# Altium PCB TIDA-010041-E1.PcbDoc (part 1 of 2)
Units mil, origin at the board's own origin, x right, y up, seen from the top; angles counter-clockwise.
Board outline 3937.01 x 2165.35 mil, 2 copper layers (Top Layer, Bottom Layer), stack 62 mil thick; 146 components, 79 nets, 325 pads, 93 vias.
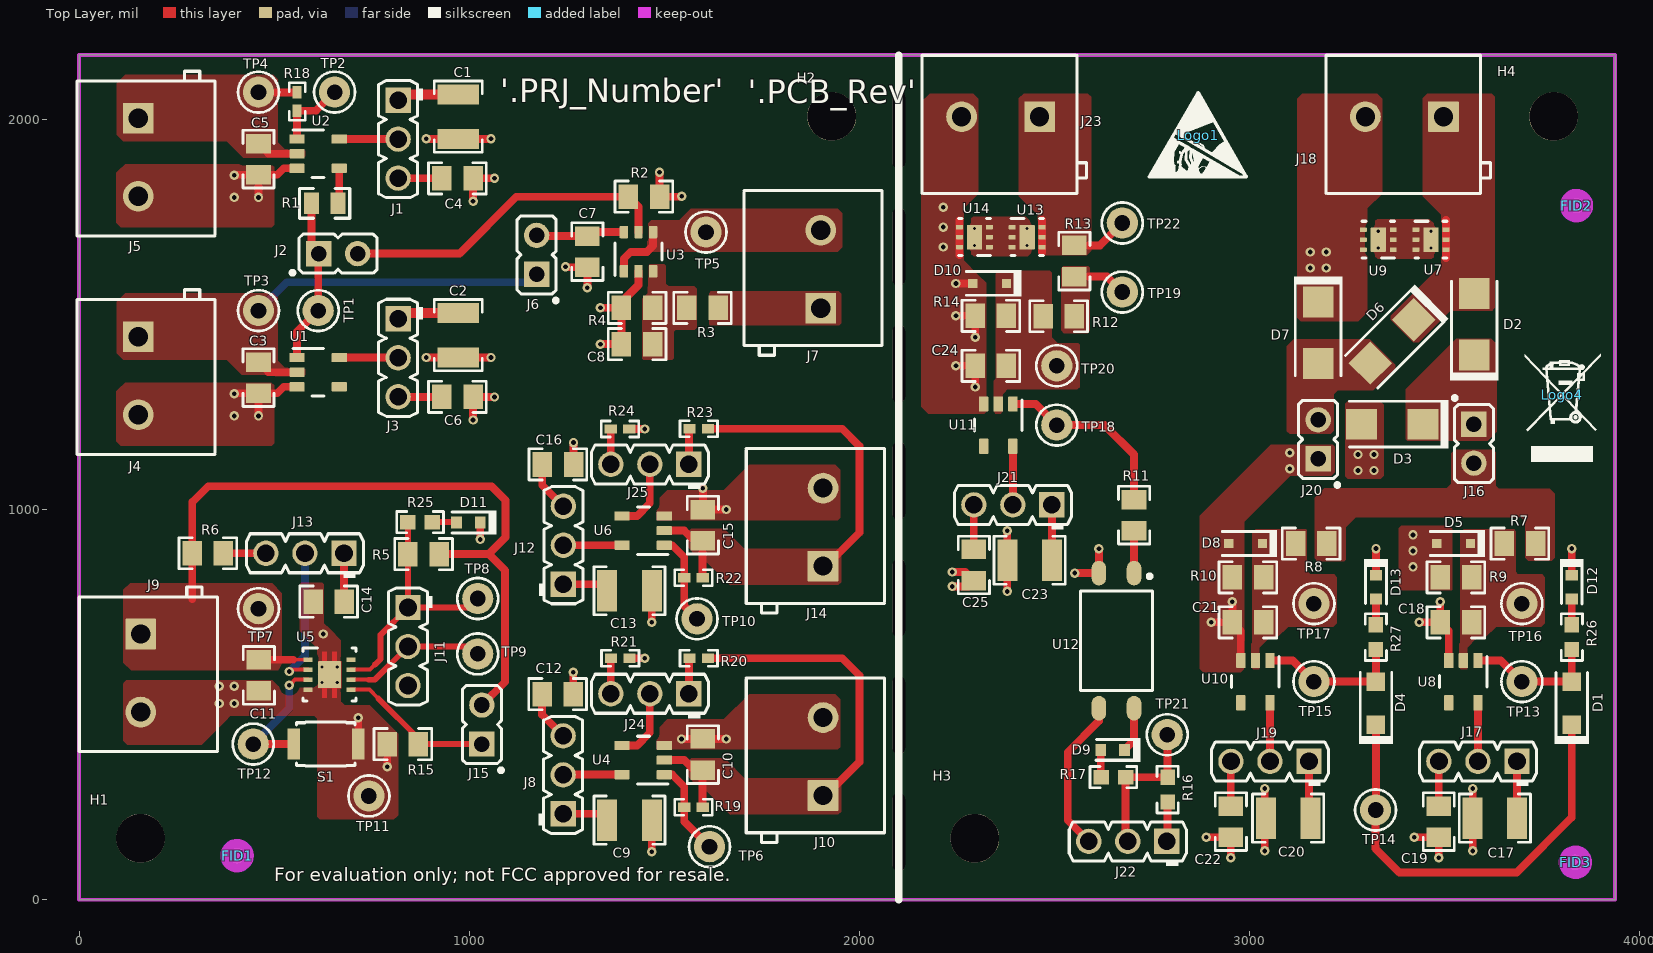
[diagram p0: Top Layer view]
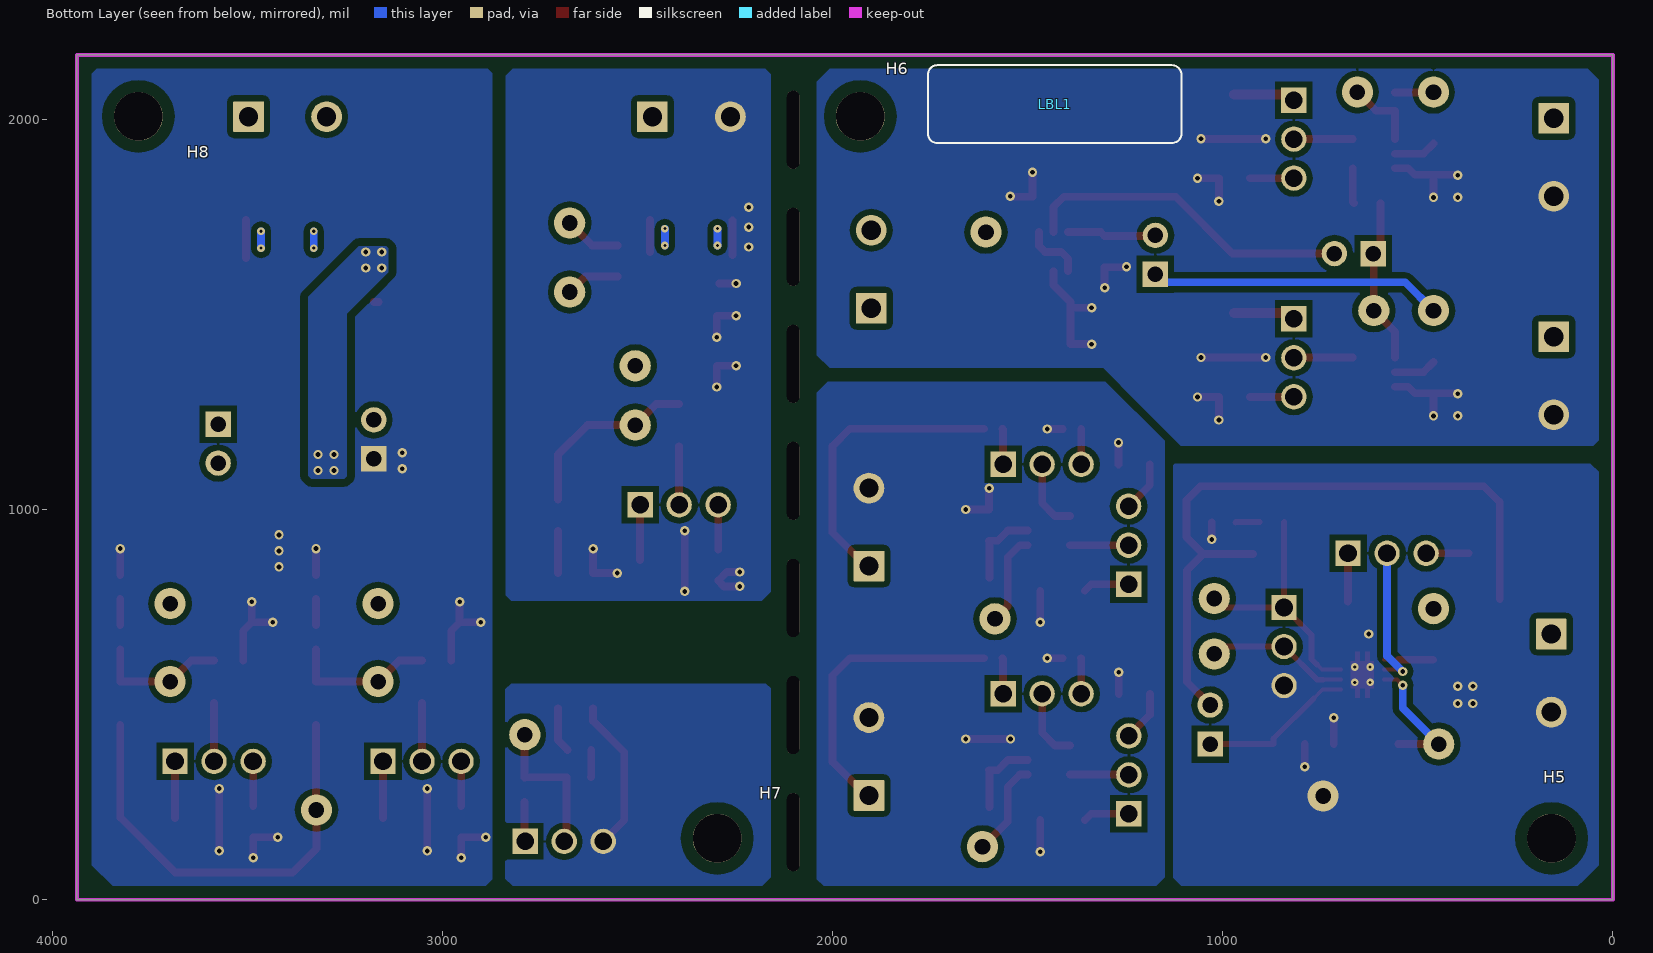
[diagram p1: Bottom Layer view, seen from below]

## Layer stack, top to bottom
Top Solder: solder mask 0.4, Solder Resist, Dk 3.5
Top Layer: signal copper 1.4
Dielectric1: core 59.2, FR-4 High Tg, Dk 4.8
Bottom Layer: signal copper 1.4
Bottom Solder: solder mask 0.4, Solder Resist, Dk 3.5

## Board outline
0,0 3937.01,0 3937.01,2165.35 0,2165.35

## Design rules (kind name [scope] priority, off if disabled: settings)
AcuteAngle [All] p1: minimum=4.50000000000000E+0001 checktracksonly=FALSE
AssemblyTestPointUsage [All] p1: valid=2
BoardOutlineClearance BoardOutlineClearance_MountingHoles [OnCopper and InComponentClass('Mounting Holes')] p1: gap=30 ignorepadtopadclearanceinfootprint=FALSE
BoardOutlineClearance BoardOutlineClearance_Poly [OnCopper and InPoly] p2: gap=25 ignorepadtopadclearanceinfootprint=FALSE
BoardOutlineClearance [OnCopper and Not InComponentClass('Logo') and not InComponentClass('FiducialMark') and not InRegion(1000,500,4000,800)] p3: gap=15 ignorepadtopadclearanceinfootprint=FALSE
Clearance Clearance_MH [InPadClass('MH') vs InPoly] p1: gap=30 ignorepadtopadclearanceinfootprint=FALSE except(0: Arc-Hole Track-Hole SMDPad-Hole THPad-Hole Via-Hole Fill-Hole Poly-Hole Region-Hole Text-Hole)
Clearance Clearance_Poly_poly [InPoly vs InPoly] p2: gap=20 ignorepadtopadclearanceinfootprint=FALSE except(0: Arc-Hole Track-Hole SMDPad-Hole THPad-Hole Via-Hole Fill-Hole Poly-Hole Region-Hole Text-Hole)
Clearance Clearance_Keepouts [IsKeepOut vs InPoly] p3: gap=30 ignorepadtopadclearanceinfootprint=FALSE except(0: Arc-Hole Track-Hole SMDPad-Hole THPad-Hole Via-Hole Fill-Hole Poly-Hole Region-Hole Text-Hole)
Clearance Clearance_Poly [InPolygon] p4: gap=15 ignorepadtopadclearanceinfootprint=FALSE except(0: Arc-Hole Track-Hole SMDPad-Hole THPad-Hole Via-Hole Fill-Hole Poly-Hole Region-Hole Text-Hole)
Clearance [All] p5: gap=7.87 ignorepadtopadclearanceinfootprint=FALSE except(0: Arc-Arc Arc-SMDPad Arc-Hole Track-Hole SMDPad-Hole THPad-Hole Via-Hole Fill-Hole Poly-Hole Region-Hole Text-Hole)
ComponentClearance ComponentClearance_MountingHoles_FiducialMarks [InComponentClass('Mounting Holes') vs InComponentClass('FiducialMark')] p1: gap=10 collisioncheckmode=3 verticalgap=10 showdistances=FALSE
ComponentClearance ComponentClearance_Shunt [InComponentClass('Header') vs InComponentClass('Shunt')] p2: gap=0 collisioncheckmode=3 verticalgap=0 showdistances=FALSE
ComponentClearance ComponentClearance_Logo [InComponentClass('Logo')] p3: gap=5 collisioncheckmode=3 verticalgap=5 showdistances=FALSE
ComponentClearance ComponentClearance_ScrewToNut [(HasFootprint('NY PMS 440 0025 PH')) vs (HasFootprint('Keystone_1902C'))] p4: gap=5 collisioncheckmode=3 verticalgap=10 showdistances=FALSE
ComponentClearance ComponentClearance_MountingHoles [InComponentClass('Mounting Holes')] p5: gap=250 collisioncheckmode=3 verticalgap=100000 showdistances=FALSE
ComponentClearance ComponentClearance_SmallPassives [HasFootprint('0201*') or HasFootprint('0402*') or HasFootprint('0508') or HasFootprint('0603*') or HasFootprint('0612') or HasFootprint('0805*') or HasFootprint('0815*') or HasFootprint('0830*') or HasFootprint('1206*') or HasFootprint('1210*') or HasFootprint('1808*') or HasFootprint('1812*') or HasFootprint('1825*') or HasFootprint('2010*') or HasFootprint('2220*') or HasFootprint('2225*') or HasFootprint('2512*') or HasFootprint('2728*') or HasFootprint('3518*') vs HasFootprint('0201*') or HasFootprint('0402*') or HasFootprint('0508') or HasFootprint('0603*') or HasFootprint('0612') or HasFootprint('0805*') or HasFootprint('0815*') or HasFootprint('0830*') or HasFootprint('1206*') or HasFootprint('1210*') or HasFootprint('1808*') or HasFootprint('1812*') or HasFootprint('1825*') or HasFootprint('2010*') or HasFootprint('2220*') or HasFootprint('2225*') or HasFootprint('2512*') or HasFootprint('2728*') or HasFootprint('3518*')] p6: gap=5 collisioncheckmode=3 verticalgap=5 showdistances=FALSE
ComponentClearance ComponentClearance_THtoSMT [IsThruComponent vs IsSMTComponent] p7: gap=5 collisioncheckmode=3 verticalgap=5 showdistances=FALSE
ComponentClearance ComponentClearance_THtoTH [IsThruComponent vs IsThruComponent] p8: gap=0 collisioncheckmode=3 verticalgap=10 showdistances=FALSE
ComponentClearance [All] p9: gap=10 collisioncheckmode=3 verticalgap=10 showdistances=FALSE
DiffPairsRouting [All] p1: maxlimit=100 minlimit=10 mostfreqgap=10 toplayer_minwidth=15 toplayer_maxwidth=15 toplayer_prefwidth=15 bottomlayer_minwidth=15 bottomlayer_maxwidth=15 bottomlayer_prefwidth=15 maxuncoupledlength=1000
FabricationTestPointUsage TestPointUsage [All] p1: valid=2 allowmultiple=FALSE
FabricationTestpoint Testpoint [All] p1: side=3 testpointundercomponent=TRUE minsize=40 maxsize=100 preferedsize=60 minholesize=0 maxholesize=40 preferedholesize=32 testpointgrid=1 allowsidetop=TRUE allowsidebottom=TRUE usegrid=TRUE gridtolerance=0.01
FanoutControl Fanout_LCC [IsLCC] p1: bgadir=Out bgaviamode=Centered fanoutstyle=Auto fanoutdirection=Alternating viagrid=1 // Fanout_LCC (Default Rule)
FanoutControl Fanout_BGA [IsBGA] p2: bgadir=Out bgaviamode=Centered fanoutstyle=Auto fanoutdirection=Alternating viagrid=1 // Fanout_BGA (Default Rule)
FanoutControl Fanout_Default [All] p4: bgadir=Out bgaviamode=Centered fanoutstyle=Auto fanoutdirection=Alternating viagrid=1 // Fanout_Default (Default Rule)
FanoutControl Fanout_Small [(CompPinCount < 5)] p5: bgadir=Out bgaviamode=Centered fanoutstyle=Auto fanoutdirection=OutThenIn viagrid=1 // Fanout_Small (Default Rule)
Height [All] p1: minheight=0 maxheight=99999 prefheight=500
HoleSize [All] p1: absolutevalues=TRUE maxlimit=251 minlimit=7.87 maxpercent=80.000 minpercent=20.000
MinimumAnnularRing MinimumAnnularRing_ThermalPadVias [IsVia and InAnyComponent] p1: minimumring=4
MinimumAnnularRing [All] p2: minimumring=4
MinimumSolderMaskSliver MinimumSolderMaskSliver_Logo [InComponentClass('Logo') vs InComponentClass('Logo')] p1: minsoldermaskwidth=0.7
MinimumSolderMaskSliver [All] p2: minsoldermaskwidth=3.94
PlaneClearance [All] p1: clearance=10
PlaneConnect [All] p1: planeconnectstyle=Relief reliefexpansion=10 reliefentries=4 reliefconductorwidth=10 reliefairgap=10
PolygonConnect PolygonConnectThermalVia [isvia] p1: connectstyle=Direct reliefconductorwidth=10 reliefentries=4 polygonreliefangle="90 Angle" airgapwidth=10
PolygonConnect PolygonConnectThermalPad [((ObjectKind = 'Pad') And (((Name Like 'U*') or (Name Like 'D*')) and (InComponentClass('TIDA-00183_pg-4_Driver') or InComponentClass('TIDA-00183_pg-5_OP_Connector')))) or ((ObjectKind = 'Pad') And (Name like 'U61*'))] p2: connectstyle=Direct reliefconductorwidth=10 reliefentries=4 polygonreliefangle="90 Angle" airgapwidth=10
PolygonConnect [All] p3: connectstyle=Direct reliefconductorwidth=10 reliefentries=4 polygonreliefangle="90 Angle" airgapwidth=5
RoutingVias ThermalPadVias [IsVia and InAnyComponent] p1: holewidth=7.87 width=19.68 viastyle="Through Hole" minholewidth=7.87 minwidth=19.68 maxholewidth=12.99 maxwidth=23.62
RoutingVias [All] p2: holewidth=16 width=32 viastyle="Through Hole" minholewidth=12 minwidth=24 maxholewidth=40 maxwidth=65
SilkToBoardRegionClearance [Not ((IsComment or IsDesignator) And (Hide <> 'False')) and not InRegion(1000,500,4000,800)] p1:
SilkToSilkClearance SilkToSilkClearance_Pb-FreeLogo [(HasFootprint('Pb-Free_Overlay_Medium') OR HasFootprint('Pb-Free_Overlay_Small')) vs (HasFootprint('Pb-Free_Overlay_Medium') OR HasFootprint('Pb-Free_Overlay_Small'))] p1: silktosilkclearance=0
SilkToSilkClearance [All] p2: silktosilkclearance=4
SilkToSolderMaskClearance SilkToComponentPadClearance [IsPad and InAnycomponent] p1: minsilkscreentomaskgap=5 clearancetoexposedcopper=TRUE
SilkToSolderMaskClearance "Silk to Solder Mask Opening" [All] p2: minsilkscreentomaskgap=4 clearancetoexposedcopper=FALSE
SolderMaskExpansion [All] p1: expansion=1.97
Width [All] p1: maxlimit=100 minlimit=6 preferedwidth=10 checkconnectedcopper=TRUE
13 further rules are at their usual default settings.

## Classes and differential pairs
component class Label: LBL1
pad class MH: H1-1 H2-1 H3-1 H4-1 H5-0 H6-0 H7-0 H8-0
component class TIDA-010041-E1_EVM_Hardware: FID1 FID2 FID3 H1 H2 H3 H4 H5 H6 H7 H8 LBL1 Logo1 Logo3 Logo4 ZZ1 ZZ2 ZZ3 ZZ4
component class FiducialMark: FID1 FID2 FID3
component class AssemblyNote: ZZ1 ZZ2 ZZ3 ZZ4
component class Header: J1 J2 J3 J6 J8 J11 J12 J13 J15 J16 J17 J19 J20 J21 J22 J24 J25
component class "TIDA-010041-E1_Power sequencing, Reset, WDT": C1 C2 C3 C4 C5 C6 C7 C8 C9 C10 C11 C12 C13 C14 C15 C16 D11 J1 J2 J3 J4 J5 J6 J7 J8 J9 J10 J11 J12 J13 J14 J15 J24 J25 R1 R2 R3 R4 R5 R6 R15 R18 R19 R20 R21 R22 R23 R24 R25 S1 TP1 TP2 TP3 TP4 TP5 TP6 TP7 TP8 TP9 TP10 TP11 TP12 U1 U2 U3 U4 U5 U6
component class "TIDA-010041-E1_Threshold detection": C17 C18 C19 C20 C21 C22 C23 C24 C25 D1 D2 D3 D4 D5 D6 D7 D8 D9 D10 D12 D13 J16 J17 J18 J19 J20 J21 J22 J23 R7 R8 R9 R10 R11 R12 R13 R14 R16 R17 R26 R27 TP13 TP14 TP15 TP16 TP17 TP18 TP19 TP20 TP21 TP22 U7 U8 U9 U10 U11 U12 U13 U14

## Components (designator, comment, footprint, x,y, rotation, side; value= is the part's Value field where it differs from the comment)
C1 "C3225X7R1H105K160AA" 1210_180 972,2007 r270 top value=1uF
C2 "C3225X7R1H105K160AA" 1210_180 972,1447 r270 top value=1uF
C3 "08053C104JAT2A" 0805_HV 460,1338 r270 top value=0.1uF
C4 "08055C103JAT2A" 0805_HV 970,1849 r0 top value=0.01uF
C5 "08053C104JAT2A" 0805_HV 460,1898 r270 top value=0.1uF
C6 "08055C103JAT2A" 0805_HV 970,1289 r0 top value=0.01uF
C7 "08053C104JAT2A" 0805_HV 1302.89,1660.89 r90 top value=0.1uF
C8 "08053C104JAT2A" 0805_HV 1430.33,1424 r180 top value=0.1uF
C9 "C3225X7R1H105K160AA" 1210_180 1410.89,204 r0 top value=1uF
C10 "08053C104JAT2A" 0805_HV 1598.89,372 r270 top value=0.1uF
C11 "08055C103JAT2A" 0805_HV 461,575 r270 top value=0.01uF
C12 "08055C103JAT2A" 0805_HV 1226.89,527 r0 top value=0.01uF
C13 "C3225X7R1H105K160AA" 1210_180 1410.89,792 r0 top value=1uF
C14 "08055C103JAT2A" 0805_HV 640,764 r180 top value=0.01uF
C15 "08053C104JAT2A" 0805_HV 1598.89,960 r270 top value=0.1uF
C16 "08055C103JAT2A" 0805_HV 1227.49,1115.6 r0 top value=0.01uF
C17 "C3225X7R1H105K160AA" 1210_180 3629,209 r180 top value=1uF
C18 "08053C104JAT2A" 0805_HV 3529,711 r0 top value=0.1uF
C19 "08055C103JAT2A" 0805_HV 3485,200 r270 top value=0.01uF
C20 "C3225X7R1H105K160AA" 1210_180 3098.91,209 r180 top value=1uF
C21 "08053C104JAT2A" 0805_HV 2996,711 r0 top value=0.1uF
C22 "08055C103JAT2A" 0805_HV 2952,200 r270 top value=0.01uF
C23 "C3225X7R1H105K160AA" 1210_180 2436.31,870.1 r180 top value=1uF
C24 "08053C104JAT2A" 0805_HV 2337,1368.5 r0 top value=0.1uF
C25 "08055C103JAT2A" 0805_HV 2293.4,857.9 r270 top value=0.01uF
D1 "PMEG2010AEH" SOD-123F 3826,503.62 r90 top value=20V
D2 "ES1B-13-F" SMA 3576,1474.95 r90 top value=100V
D3 "ES1B-13-F" SMA 3366,1219 r180 top value=100V
D4 "PMEG2010AEH" SOD-123F 3324,503.62 r90 top value=20V
D5 "MMSZ5227BS-7-F" SOD-323 3523,913 r180 top value=3.6V
D6 "ES1B-13-F" SMA 3365,1431 r225 top value=100V
D7 "ES1B-13-F" SMA 3176,1453 r270 top value=100V
D8 "MMSZ5227BS-7-F" SOD-323 2990,913.01 r180 top value=3.6V
D9 "LNJ337W83RA" LNJx37x8_Green 2649,384 r180 top value=Green
D10 "MMSZ5227BS-7-F" SOD-323 2334,1579.5 r180 top value=3.6V
D11 "LNJ337W83RA" LNJx37x8_Green 998,967 r180 top value=Green
D12 "LNJ337W83RA" LNJx37x8_Green 3826,801 r270 top value=Green
D13 "LNJ337W83RA" LNJx37x8_Green 3324,801 r270 top value=Green
FID1 "Fiducial" Fiducial10-20 405,113 r90 top
FID2 "Fiducial" Fiducial10-20 3838,1779 r90 top
FID3 "Fiducial" Fiducial10-20 3835,96 r90 top
H1 "NSP-4-3-01" B_F_PMSSS4400025PH 157.48,157.48 r0 top
H2 "NSP-4-3-01" B_F_PMSSS4400025PH 1929.13,2007.87 r0 top
H3 "NSP-4-3-01" B_F_PMSSS4400025PH 2296,157.48 r0 top
H4 "NSP-4-3-01" B_F_PMSSS4400025PH 3779.53,2007.87 r0 top
H5 "1902E" Keystone_1902E 157.48,157.48 r180 bottom
H6 "1902E" Keystone_1902E 1929.13,2007.87 r180 bottom
H7 "1902E" Keystone_1902E 2296,157.48 r180 bottom
H8 "1902E" Keystone_1902E 3779.53,2007.87 r180 bottom
J1 "61300311121" WURTH_61300311121 818,1949.4 r270 top
J2 "PBC02SAAN" Sullins_PBC02SAAN 664,1656 r90 top
J3 "61300311121" WURTH_61300311121 818,1389 r270 top
J4 "ED120/2DS" On-Shore_ED120_2DS 152,1343 r270 top
J5 "ED120/2DS" On-Shore_ED120_2DS 152,1903 r270 top
J6 "PBC02SAAN" Sullins_PBC02SAAN 1172.89,1652.89 r180 top
J7 "ED120/2DS" On-Shore_ED120_2DS 1900.89,1615.89 r90 top
J8 "61300311121" WURTH_61300311121 1240.89,320 r90 top
J9 "ED120/2DS" On-Shore_ED120_2DS 158,581 r270 top
J10 "ED120/2DS" On-Shore_ED120_2DS 1906.89,367 r90 top
J11 "61300311121" WURTH_61300311121 843,649 r270 top
J12 "61300311121" WURTH_61300311121 1241.49,908.6 r90 top
J13 "61300311121" WURTH_61300311121 579,888 r180 top
J14 "ED120/2DS" On-Shore_ED120_2DS 1906.89,955 r90 top
J15 "PBC02SAAN" Sullins_PBC02SAAN 1032.45,449 r180 top
J16 "PBC02SAAN" Sullins_PBC02SAAN 3575,1169 r0 top
J17 "61300311121" WURTH_61300311121 3585.4,354.6 r180 top
J18 "ED120/2DS" On-Shore_ED120_2DS 3397,2007 r180 top
J19 "61300311121" WURTH_61300311121 3052.4,354.6 r180 top
J20 "PBC02SAAN" Sullins_PBC02SAAN 3176,1180 r180 top
J21 "61300311121" WURTH_61300311121 2393.4,1012.1 r180 top
J22 "61300311121" WURTH_61300311121 2688,149.5 r180 top
J23 "ED120/2DS" On-Shore_ED120_2DS 2362,2007 r180 top
J24 "61300311121" WURTH_61300311121 1463,528 r180 top
J25 "61300311121" WURTH_61300311121 1463,1116 r180 top
LBL1 "THT-14-423-10" Label_650x200 1431,2039 r0 bottom
Logo1 "ESD Susceptible" ESD_Overlay_Medium 2868.06,1959.8 r0 top
Logo3 "FCC disclaimer" FCC_disclaimer 4617.39,587.82 r90 top
Logo4 "WEEE logo" WEEE_Minimum 3801.39,1294.82 r0 top
R1 "5106" 5106 629,1785 r0 top value=0
R2 "MCU08050C1002FP500" 0805_HV 1447.89,1801.89 r180 top value=10.0k
R3 "MCU08050C1003FP500" 0805_HV 1598,1517 r0 top value=100k
R4 "MCU08050C1003FP500" 0805_HV 1430.33,1517 r0 top value=100k
R5 "PLTT0805Z1002QGT5" 0805_HV 883,886 r180 top value=10.0k
R6 "PLTT0805Z1002QGT5" 0805_HV 330,888 r0 top value=10.0k
R7 "RG2012P-161-B-T5" 0805_HV 3693,913 r0 top value=160
R8 "ERJ-6ENF49R9V" 0805_HV 3158,913 r0 top value=49.9
R9 "CRCW080540R2FKEA" 0805_HV 3529,826 r0 top value=40.2
R10 "RG2012P-151-B-T5" 0805_HV 2996,826 r0 top value=150
R11 "RR1220P-152-D" 0805_HV 2704,985.5 r270 top value=1.50k
R12 "ERJ-6GEYJ204V" 0805_HV 2511,1495.5 r0 top value=200k
R13 "RG2012P-102-B-T5" 0805_HV 2551,1637 r270 top value=1.00k
R14 "ERJ-6GEYJ204V" 0805_HV 2337,1496.5 r0 top value=200k
R15 "PLTT0805Z1002QGT5" 0805_HV 830,399 r180 top value=10.0k
R16 "ERJ-3EKF1000V" 0603 2790,282 r270 top value=100
R17 "ERJ-3GEY0R00V" 0603 2651,314 r0 top value=0
R18 "ERJ-2RKF1002X" 0402 559,2045.62 r90 top value=10.0k
R19 "ERJ-2RKF1002X" 0402 1575,237 r0 top value=10.0k
R20 "ERJ-2RKF1002X" 0402 1588.38,619 r0 top value=10.0k
R21 "ERJ-2RKF1002X" 0402 1387,619 r180 top value=10.0k
R22 "ERJ-2RKF1002X" 0402 1575,825 r0 top value=10.0k
R23 "ERJ-2RKF1002X" 0402 1588.38,1207 r0 top value=10.0k
R24 "ERJ-2RKF1002X" 0402 1386.62,1206.62 r180 top value=10.0k
R25 "RG1608P-332-B-T5" 0603 874,968 r0 top value=3.30k
R26 "CRCW06033K00JNEA" 0603 3826,673 r270 top value=3.0k
R27 "CRCW06033K00JNEA" 0603 3324,673 r270 top value=3.0k
S1 "SKRKAEE010" SW_SKRKAEE010 633,399 r180 top
TP1 "" Keystone5000 613,1509.83 r90 top
TP2 "" Keystone5000 655,2070 r90 top
TP3 "" Keystone5000 460,1510 r270 top
TP4 "" Keystone5000 460,2069.83 r270 top
TP5 "" Keystone5000 1607,1711.09 r270 top
TP6 "" Keystone5000 1616,136 r270 top
TP7 "" Keystone5000 460,746 r270 top
TP8 "" Keystone5000 1022,772 r270 top
TP9 "" Keystone5000 1022,630 r270 top
TP10 "" Keystone5000 1584,720 r270 top
TP11 "" Keystone5000 743,266 r270 top
TP12 "" Keystone5000 446.51,399 r90 top
TP13 "" Keystone5000 3698,559 r90 top
TP14 "" Keystone5000 3323,230 r90 top
TP15 "" Keystone5000 3165,559 r90 top
TP16 "" Keystone5000 3698,759 r90 top
TP17 "" Keystone5000 3165,759 r90 top
TP18 "" Keystone5000 2506,1216.5 r90 top
TP19 "" Keystone5000 2674,1557.5 r90 top
TP20 "" Keystone5000 2506,1368.5 r90 top
TP21 "" Keystone5000 2789,423 r90 top
TP22 "" Keystone5000 2674,1734.5 r90 top
U1 "TPS3840PL28DBVR" DBV0005A_N 613,1352 r0 top
U2 "TPS3840PL28DBVR" DBV0005A_N 613,1912 r0 top
U3 "OPA320SAIDBVR" DBV0006A_L 1433.89,1660.89 r90 top
U4 "TPS3840DL27DBVR" DBV0005A_N 1445.89,358 r180 top
U5 "TPS3431SDRBR" DRB0008A 642.12,576.8 r0 top
U6 "TPS3840PH30DBVR" DBV0005A_N 1445.89,946 r180 top
U7 "TVS0500DRVR" DRV0006A 3465,1691.72 r0 top
U8 "TPS3840PL28DBVR" DBV0005A_N 3548,559 r270 top
U9 "TVS0500DRVR" DRV0006A 3330,1691.72 r180 top
U10 "TPS3840PL28DBVR" DBV0005A_N 3015,559 r270 top
U11 "TPS3840PL28DBVR" DBV0005A_N 2356,1216.5 r270 top
U12 "CPC1303GR" IXYS_CPC1303GR 2659,664 r270 top
U13 "TVS1400DRVR" DRV0006A 2430,1698.22 r0 top
U14 "TVS0500DRVR" DRV0006A 2295,1698.22 r180 top
ZZ1 "This Assembly Note is for PCB labels only" AssemblyNoteLabel 45.81,3845.4 r0 top
ZZ2 "These assemblies are ESD sensitive, ESD precautions shall be observed." AssemblyNote 42.81,3739.52 r0 top
ZZ3 "These assemblies must be clean and free from flux and all contaminants. Use of no clean flux is not acceptable." AssemblyNote 42.81,3650.96 r0 top
ZZ4 "These assemblies must comply with workmanship standards IPC-A-610 Class 2, unless otherwise specified." AssemblyNote 42.81,3562.4 r0 top

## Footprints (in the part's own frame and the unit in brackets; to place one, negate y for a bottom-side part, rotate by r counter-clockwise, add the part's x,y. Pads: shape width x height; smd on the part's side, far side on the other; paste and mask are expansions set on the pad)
0402 [mm] "0402 from SM-752 data"
  rect 0.8x0.6 smd: 1(-0.6,0) 2(0.6,0)
  silkscreen extent -1.22,-0.52 1.22,0.52, body extent -0.55,-0.3 0.55,0.3, height 0.6
0603 [mm] "0603 from SM-752 data"
  rect 1x0.95 smd: 1(-0.8,0) 2(0.8,0)
  silkscreen extent -1.52,-0.69 1.52,0.69, body extent -0.87,-0.47 0.87,0.47, height 1
0805_HV [mil] "0805 with 30mil clearance between pads"
  rect 50x63 smd: 1(-40,0) 2(40,0)
  silkscreen extent -74,-40 74,40, body extent -43,-29 43,29, height 57
1210_180 [mm] "1210"
  rect 1.3x2.7 smd: 1(-1.45,0) 2(1.45,0)
  silkscreen extent -2.32,-1.57 2.32,1.57, body extent -1.7,-1.35 1.7,1.35, height 1.8
5106 [mm] "Keystone"
  rect 0.99x1.4 smd: 1(-0.85,0) 2(0.88,0)
  silkscreen extent -1.63,-0.97 1.65,0.97, body extent -1.06,-0.69 1.06,0.69, height 0.84
AssemblyNote [mil] "Assembly Note"
AssemblyNoteLabel [mil] "Assembly Note for PCB Labels"
B_F_PMSSS4400025PH [mil] "MACHINE SCREW PAN PHILLIPS 4-40"
  round 125 hole 125 unplated mask+10: 1(0,0)
  body extent -109,-109 110,110, height 79
DBV0005A_N [mm] "SOT23, 5-Leads, Body 2.9x1.6mm, Pitch 0.95mm, Lead Span 2.8mm, IPC Medium Density"
  rrect17% 1x0.6 smd: 1(-1.375,0.95) 2(-1.375,0) 3(-1.375,-0.95) 4(1.375,-0.95) 5(1.375,0.95)
  silkscreen extent -1.63,-1.55 0.38,1.55, body extent -1.42,-1.46 1.42,1.46, height 1.09
DBV0006A_L [mm] "SOT23, 6-Leads, Body 2.9x1.6mm, Pitch 0.95mm, Lead Span 2.8mm, IPC High Density"
  rrect18% 0.8x0.55 smd: 1(-1.275,0.95) 2(-1.275,0) 3(-1.275,-0.95) 4(1.275,-0.95) 5(1.275,0) 6(1.275,0.95)
  silkscreen extent -1.55,-1.53 0.55,1.53, body extent -1.42,-1.46 1.42,1.46, height 1.12
DRB0008A [mm] "SON, 8-Leads, Body 3x3mm, Pitch 0.65mm, Thermal Pad 1.75x1.5mm, TI Recommended"
  rrect33% 0.6x0.3 smd: 1(-1.4,0.975) 2(-1.4,0.325) 3(-1.4,-0.325) 4(-1.4,-0.975) 5(1.4,-0.975) 6(1.4,-0.325) 7(1.4,0.325) 8(1.4,0.975)
  rrect7% 1.5x1.75 smd paste-0.75: 9(0,0)
  Top Layer region: -0.465,-1.5 -0.465,-0.875 -0.75,-0.875 -0.75,0.875 -0.465,0.875 -0.465,1.5 -0.185,1.5 -0.185,0.875 0.185,0.875 0.185,1.5 0.465,1.5 0.465,0.875 0.75,0.875 0.75,-0.875 0.465,-0.875 0.465,-1.5 0.185,-1.5 0.185,-0.875 -0.185,-0.875 -0.185,-1.5
  silkscreen extent -1.73,-1.73 1.73,1.73, body extent -1.58,-1.57 1.57,1.58, height 1.01
DRV0006A [mm] "SON, 6-Leads, Body 2x2mm, Pitch 0.65mm, Thermal Pad 1.6x1mm, TI Recommended"
  rrect33% 0.45x0.3 smd: 1(-0.975,0.65) 2(-0.975,0) 3(-0.975,-0.65) 4(0.975,-0.65) 5(0.975,0) 6(0.975,0.65)
  rrect14% 1x0.7 on Top Paste: 7(0,-0.45) 7(0,0.45)
  rrect10% 1x1.6 smd paste-0.5: 7(0,0)
  silkscreen extent -1.05,-1.2 1.05,1.2, body extent -1.05,-1.05 1.05,1.05, height 0.81
ESD_Overlay_Medium [mil]
  silkscreen extent -127,-109 125,110
FCC_disclaimer [mil]
Fiducial10-20 [mm]
  round 1 smd mask+0.5: 1(0,0)
  Top Layer keep-out circle w1.178: c0,0 r0.5
IXYS_CPC1303GR [mm] "IXYS"
  oval 1.6x0.95 smd: 1(-4.4,1.144) 2(-4.4,-1.144) 3(4.4,-1.144) 4(4.4,1.144)
  silkscreen extent -4.32,-2.35 3.24,2.35, body extent -3.24,-2.35 3.24,2.35, height 3.56
Keystone5000 [mil] "For Keystone 500x miniature loop terminals"
  round 80 hole 40: 1(0,0)
  silkscreen extent -52,-52 52,52, body extent -49,-49 49,49, height 182
Keystone_1902E [mil] "Hex Standoff, 4-40 threaded, nylon"
  round 1 on Mech4: 0(0,0)
  body extent -145,-126 146,126, height 1001
Label_650x200 [mil] "Thermal Transfer Label"
  round 1 on Mech14: 0(0,0)
  silkscreen extent -325,-100 325,100, body extent -325,-100 325,100, height 1
LNJx37x8_Green [mm] "SMD, 2-Leads, Body 1.6x0.8mm"
  rect 0.7x0.8 smd: 1(0.775,0) 2(-0.775,0)
  silkscreen extent -1.82,-0.78 1.07,0.77, body extent -0.85,-0.45 0.85,0.45, height 0.25
On-Shore_ED120_2DS [mm] "ONSHORE"
  rrect5% 2x2 hole 1.25: 1(-2.54,0)
  round 2 hole 1.25: 2(2.54,0)
  silkscreen extent -5.6,-4 5.12,5, body extent -5.78,-4 5.08,5, height 13
SMA [mm] "Molded Diode, 2-Leads, Body 4.3x2.6mm, IPC Medium Density, based on OnSemi component dimensions and land pattern"
  rect 2x2 smd: 1(-2,0) 2(2,0)
  silkscreen extent -3.66,-1.57 2.79,1.57, body extent -2.6,-1.3 2.6,1.3, height 2.42
SOD-123F [mm] "NXP recommended land pattern"
  rect 1.2x1.2 smd paste-0.05: 1(-1.4,0) 2(1.4,0)
  silkscreen extent -2.64,-1.12 2.01,1.12, body extent -1.8,-0.85 1.8,0.85, height 1.2
SOD-323 [mm] "NXP recommended land pattern"
  rect 0.6x0.6 smd paste-0.05: 1(-1.1,0) 2(1.1,0)
  silkscreen extent -2.06,-0.86 1.53,0.86, body extent -1.3,-0.67 1.3,0.68, height 1.1
Sullins_PBC02SAAN [mm] "Sullins 100mil, 1x2, 230 mil above insulator"
  rect 1.65x1.65 hole 1.016: 1(0,1.27)
  round 1.65 hole 1.016: 2(0,-1.27)
  silkscreen extent -1.37,-2.54 1.27,3.1, body extent -1.27,-2.54 1.27,2.54, height 8.38
SW_SKRKAEE010 [mm] "Alps recommended land pattern"
  rect 0.8x2 smd: 1(-2.1,0) 2(2.1,0)
  silkscreen extent -1.9,-1.44 1.92,1.44, body extent -2.4,-1.45 2.4,1.45, height 1.96
WEEE_Minimum [mil] "WEEElie bin"
  silkscreen extent -95,-172 99,104
WURTH_61300311121 [mm] "Header, 2.54mm, 3x1, TH"
  rect 1.65x1.65 hole 1.15: 1(-2.54,0)
  round 1.65 hole 1.15: 2(0,0) 3(2.54,0)
  silkscreen extent -3.81,-1.27 3.81,1.6, body extent -3.81,-1.27 3.81,1.27, height 8.54

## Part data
C1 C2 C9 C13 C17 C20 C23: library part CMP-0009119-1, "CAP, CERM, 1 uF, 50 V, +/- 10%, X7R, 1210", Cap_Case=1210_180, Manufacturer=TDK, Supplier Part Number 1=445-7722-1-ND, TempCo=X7R, Tolerance_%=10%, Value1="0.007168 ohm", Value2=50V, ValueDisplayed=1uF
C3 C5 C7 C8 C10 C15 C18 C21 C24: library part CMP-0007565-2, "CAP, CERM, 0.1 uF, 25 V, +/- 5%, X7R, 0805", Cap_Case=0805, Manufacturer=AVX, Supplier Part Number 1=478-7946-1-ND, TempCo=X7R, Tolerance_%=5%, Value1=Unknown, Value2=25V, ValueDisplayed=0.1uF
C4 C6 C11 C12 C14 C16 C19 C22 C25: library part CMP-0007629-2, "CAP, CERM, 0.01 uF, 50 V, +/- 5%, X7R, 0805", Cap_Case=0805, Manufacturer=AVX, Supplier Part Number 1=478-3768-1-ND, TempCo=X7R, Tolerance_%=5%, Value1="0.078 ohm", Value2=50V, ValueDisplayed=0.01uF
D1 D4: library part CMP-0077033-2, "Diode, Schottky, 20 V, 1 A, SOD-123F", Manufacturer=Nexperia, PartNumber=PMEG2010AEH,115, Value1=1A, Value2=0.43V
D2 D3 D6 D7: library part CMP-0029022-1, "Diode, Superfast Rectifier, 100 V, 1 A, SMA", Manufacturer="Diodes Inc.", Supplier Part Number 1=ES1B-FDICT-ND, Value1=1A, Value2=0.92V
D5 D8 D10: library part CMP-0005850-1, "Diode, Zener, 3.6 V, 200 mW, SOD-323", Manufacturer="Diodes Inc.", Power_W=200mW, Supplier Part Number 1=MMSZ5227BS-FDICT-ND, Value1=0.2W
D9 D11 D12 D13: library part CMP-0002976-2, "LED, Green, SMD", Color=Green, Manufacturer=Panasonic, Supplier Part Number 1=LNJ337W83RACT-ND, Value1=W, Value2=1.95V
FID1 FID2 FID3: library part CMP-0077181-1, "Fiducial mark.  There is nothing to buy or mount.", Manufacturer=N/A
H1 H2 H3 H4: library part "PMSSS 440 0025 PH", "MACHINE SCREW PAN PHILLIPS 4-40", Manufacturer="Essentra Components", Supplier Part Number 1=RPC1579-ND
H5 H6 H7 H8: "Standoff, Hex, 1\"L #4-40 Nylon", Manufacturer=Keystone, Supplier Part Number 1=36-1902E-ND
J1 J3 J8 J11 J12 J13 J17 J19 J21 J22 J24 J25: library part CMP-0054796-1, "Header, 2.54 mm, 3x1, Gold, TH", Manufacturer="Wurth Elektronik", Supplier Part Number 1=732-5316-ND
J2 J6 J15 J16 J20: library part CMP-0054566-1, "Header, 100mil, 2x1, Gold, TH", Color=Black, Current_A=3A, Manufacturer="Sullins Connector Solutions", Supplier Part Number 1=S1011E-02-ND, Voltage_V=1.8kV
J4 J5 J7 J9 J10 J14 J18 J23: library part CMP-0074910-1, "Terminal Block, 5.08 mm, 2x1, Brass, TH", Color=Blue, Current_A=15A, Manufacturer="On-Shore Technology", Supplier Part Number 1=ED1609-ND, Voltage_V=300V
LBL1: library part CMP-0003625-1, "Thermal Transfer Printable Labels, 0.650\" W x 0.200\" H - 10,000 per roll", Manufacturer=Brady, Supplier Part Number 1=97C5133
Logo1: library part ESD_Susceptible, "ESD Susceptible Symbol"
Logo3: library part CMP-0074847-1, "FCC_disclaimer"
Logo4: library part CMP-0074769-1
R1: library part CMP-0020833-2, "RES, 0, 1%, 0.5 W, 0805", Manufacturer=Keystone, Power_W=500mW, Supplier Part Number 1=36-5106CT-ND, TempCo=ppm/C, Tolerance_%=1%, Value2=0.5W, Value_Code=0
R2: library part CMP-0021857-2, "RES, 10.0 k, 1%, 0.2 W, 0805", Manufacturer=Vishay/Beyschlag, Power_W=200mW, Supplier Part Number 1=MCU0805-10.0K-CFCT-ND, TempCo="50 ppm/C", Tolerance_%=1%, Value2=0.2W, Value_Code=10k0, ValueDisplayed=10.0k
R3 R4: library part CMP-0021858-2, "RES, 100 k, 1%, 0.2 W, 0805", Manufacturer=Vishay/Beyschlag, Power_W=200mW, Supplier Part Number 1=MCU0805-100K-CFCT-ND, TempCo="50 ppm/C", Tolerance_%=1%, Value2=0.2W, Value_Code=100k
R5 R6 R15: library part CMP-0018847-1, "RES, 10.0 k, 0.02%, 0.25 W, 0805", Manufacturer=Vishay-Dale, Power_W=250mW, Supplier Part Number 1=PLTT10.0KACT-ND, TempCo="5 ppm/C", Tolerance_%=0.02%, Value2=0.25W, Value_Code=10k0, ValueDisplayed=10.0k
R7: library part CMP-0018892-2, "RES, 160, 0.1%, 0.125 W, 0805", Manufacturer="Susumu Co Ltd", Power_W=125mW, Supplier Part Number 1=RG20P160BCT-ND, TempCo="25 ppm/C", Tolerance_%=0.1%, Value2=0.125W, Value_Code=160R, ValueDisplayed=160
R8: "RES, 49.9, 1%, 0.125 W, 0805", Manufacturer=Panasonic, Power_W=0.125, Supplier Part Number 1=P49.9CDKR-ND, TempCo="100 ppm/C", Tolerance_%=1, Value1=1%, Value2=0.125W, Value_Code=49R9, ValueDisplayed=49.9
R9: "RES, 40.2, 1%, 0.125 W, 0805", Manufacturer=Vishay-Dale, Power_W=0.125, Supplier Part Number 1=541-40.2CCT-ND, TempCo="100 ppm/C", Tolerance_%=1, Value1=1%, Value2=0.125W, Value_Code=40R2, ValueDisplayed=40.2
R10: library part CMP-0018885-2, "RES, 150, 0.1%, 0.125 W, 0805", Manufacturer="Susumu Co Ltd", Power_W=125mW, Supplier Part Number 1=RG20P150BCT-ND, TempCo="25 ppm/C", Tolerance_%=0.1%, Value2=0.125W, Value_Code=150R, ValueDisplayed=150
R11: library part CMP-0019144-2, "RES, 1.50 k, 0.5%, 0.1 W, 0805", Manufacturer="Susumu Co Ltd", Power_W=100mW, Supplier Part Number 1=RR12P1.5KDCT-ND, TempCo="25 ppm/C", Tolerance_%=0.5%, Value2=0.1W, Value_Code=1k50, ValueDisplayed=1.50k
R12 R14: "RES, 200 k, 5%, 0.125 W, 0805", Manufacturer=Panasonic, Power_W=0.125, Supplier Part Number 1=P200KACT-ND, TempCo="200 ppm/C", Tolerance_%=5, Value1=5%, Value2=0.125W, Value_Code=200k
R13: library part CMP-0018855-2, "RES, 1.00 k, 0.1%, 0.125 W, 0805", Manufacturer="Susumu Co Ltd", Power_W=125mW, Supplier Part Number 1=RG20P1.0KBCT-ND, TempCo="25 ppm/C", Tolerance_%=0.1%, Value2=0.125W, Value_Code=1k00, ValueDisplayed=1.00k
R16: "RES, 100, 1%, 0.1 W, AEC-Q200 Grade 0, 0603", Manufacturer=Panasonic, Power_W=0.1, Supplier Part Number 1=P100HCT-ND, TempCo="100 ppm/C", Tolerance_%=1, Value1=1%, Value2=0.1W, Value_Code=100R, ValueDisplayed=100
R17: "RES, 0, 5%, 0.1 W, 0603", Manufacturer=Panasonic, Power_W=0.1, Supplier Part Number 1=P0.0GCT-ND, TempCo="600 ppm/C", Tolerance_%=5, Value1=5%, Value2=0.1W, Value_Code=0000, ValueDisplayed=0
R18 R19 R20 R21 R22 R23 R24: "RES, 10.0 k, 1%, 0.1 W, 0402", Manufacturer=Panasonic, Power_W=0.1, Supplier Part Number 1=P10.0KLCT-ND, TempCo="100 ppm/C", Tolerance_%=1, Value1=1%, Value2=0.1W, Value_Code=10k0, ValueDisplayed=10.0k
R25: "RES, 3.30 k, 0.1%, 0.1 W, 0603", Manufacturer="Susumu Co Ltd", Power_W=0.1, Supplier Part Number 1=RG16P3.3KBCT-ND, TempCo="25 ppm/C", Value1=0.1%, Value2=0.1W, Value_Code=3k30, ValueDisplayed=3.30k
R26 R27: "RES, 3.0 k, 5%, 0.1 W, 0603", Manufacturer=Vishay-Dale, Power_W=0.1, Supplier Part Number 1=541-3.0KGCT-ND, TempCo="200 ppm/C", Tolerance_%=5, Value1=5%, Value2=0.1W, Value_Code=3k00, ValueDisplayed=3.0k
S1: library part CMP-0002113-2, "Switch, Push Button, SMD", CurrentRating_mA=50A, Manufacturer=Alps, Supplier Part Number 1=688-SKRKAE
TP1 TP2 TP3 TP4 TP5 TP6 TP7 TP8 TP9 TP10 TP11 TP12 TP13 TP14 TP15 TP16 TP17 TP18 TP19 TP20 TP21 TP22: library part CMP-0055137-1, "Test Point, Miniature, Red, TH", Color=Red, Manufacturer=Keystone, PartNumber=5000, Supplier Part Number 1=36-5000-ND
U1 U2 U8 U10 U11: library part CMP-0079923-1, "Nano Power, Wide VIN Voltage Detector with Programmable Delay, DBV0005A (SOT-23-5)", Alternate Manufacturer="Texas Instruments"
U3: library part CMP-0075795-1, "Precision, 20MHz, 0.9pA Ib, RRIO, CMOS Operational Amplifier, DBV0006A (SOT-23-6)", Alternate Manufacturer="Texas Instruments", Alternate PartNumber=OPA320SAIDBVT
U4: library part CMP-0079925-1, "Nano Power, Wide VIN Voltage Detector with Programmable Delay, DBV0005A (SOT-23-5)", Alternate Manufacturer="Texas Instruments"
U5: library part CMP-0081798-1, "Stand Alone Watchdog with programmable timeout period, DRB0008A (VSON-8)", Alternate Manufacturer="Texas Instruments", Rating=Catalog
U6: library part CMP-0079924-1, "Nano Power, Wide VIN Voltage Detector with Programmable Delay, DBV0005A (SOT-23-5)", Alternate Manufacturer="Texas Instruments"
U7 U9 U14: library part CMP-0077837-1, "5-V Precision Surge Protection Clamp, DRV0006A (WSON-6)", Alternate Manufacturer="Texas Instruments"
U12: library part CMP-0006170-3, "Optocoupler, 5 kV, 200-2500% CTR, SMT", Manufacturer=IXYS, Supplier Part Number 1=CPC1303GR-ND, Voltage_Isolation_Vrms=5kV
U13: library part CMP-0077836-1, "14-V Precision Surge Protection Clamp, DRV0006A (WSON-6)", Alternate Manufacturer="Texas Instruments"
ZZ1: library part CMP-0003616-3
ZZ2: library part CMP-0077236-1
ZZ3: library part CMP-0077237-1
ZZ4: library part CMP-0077238-1

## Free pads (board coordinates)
  oval 32x200 hole 32 slot 200 at 90 deg unplated mask+10: 0(2101,173.42) 0(2101,473.42) 0(2101,773.42) 0(2101,1073.42) 0(2101,1373.42) 0(2101,1673.42) 0(2101,1973.42)

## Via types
v1: diameter 24, hole 12, Top Layer to Bottom Layer, 81 vias
v2: diameter 19.68, hole 7.87, Top Layer to Bottom Layer, 12 vias

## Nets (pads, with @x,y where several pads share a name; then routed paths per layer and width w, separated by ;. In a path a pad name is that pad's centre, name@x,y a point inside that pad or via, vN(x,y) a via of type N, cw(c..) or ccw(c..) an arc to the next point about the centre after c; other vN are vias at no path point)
BIN_V_IN: J23.1 R13.1 TP22.1 U13.4 U13.5 U13.6 | length 229.7
  Top Layer w20: 2468.39,1659.61 U13.4@2468.39,1672.63 U13.6@2468.39,1723.81 2468.39,1742.51 ; R13.1@2551,1677 2616.5,1677 TP22.1@2674,1734.5
GFD_1: D1.2 R26.2 TP13.1 U8.1 | length 345.9
  Top Layer w20: U8.1@3585.4,613.13 3643.87,613.13 TP13.1@3698,559 3825.74,559 D1.2@3826,558.74 R26.2@3826,641.5
GFD_2: D4.2 R27.2 TP15.1 U10.1 | length 376.9
  Top Layer w20: U10.1@3052.4,613.13 3110.87,613.13 TP15.1@3165,559 3323.74,559 D4.2@3324,558.74 R27.2@3324,641.5
GFD_OUT: D1.1 D4.1 TP14.1 | length 1142.1
  Top Layer w20: D4.1@3324,448.5 3324,231 TP14.1@3323,230 3323,131 3384,70 3685,70 3826,211 D1.1@3826,448.5
GND_BV: C23.2 C24.1 C25.2 D10.2 J23.2 R14.1 U11.3 U12.2 U14.4 U14.5 U14.6 | length 746.4
  Top Layer w20: v1@2237,840 v1(2238,840) 2271.3,840 C25.2@2293.4,817.9 2278.5,803 v1(2238,803) ; v1(2247.5,1368.5) C24.1@2297,1368.5 v1(2297,1314) ; v1(2247.5,1496.5) R14.1@2297,1496.5 v1(2297,1442) ; v1(2247.5,1579.5) D10.2@2290.69,1579.5 ; 2256.61,1652.61 U14.6@2256.61,1672.63 U14.4@2256.61,1723.81 2256.61,1740.61 ; v1(2379,946) 2379,870.33 C23.2@2379.23,870.1 v1(2379.23,790.23) ; v1(2551.86,837.23) U12.2@2613.98,837.23 v1(2613.98,899.35)
  other v1: 2215,1673 2215,1724 2215,1775
GND_GF: C17.2 C18.1 C19.2 C20.2 C21.1 C22.2 D5.2 D8.2 D12.2 D13.2 J20.1 R9.1 R10.1 U8.3 U10.3 | length 1114.3
  Top Layer w20: v1(2889,160) C22.2@2952,160 v1(2952,108) ; v1(2902,711) C21.1@2956,711 ; v1(2956,764) C21.1@2956,711 ; U10.3@2977.6,613.13 2977.6,689.4 C21.1@2956,711 ; v1(3038.91,125.09) v1(3038.91,284.91) ; D13.2@3324,831.51 v1(3324,900) ; v1(3422,160) C19.2@3485,160 v1(3485,108) ; v1(3435,711) C18.1@3489,711 ; v1(3489,764) C18.1@3489,711 ; U8.3@3510.6,613.13 3510.6,689.4 C18.1@3489,711 ; v1(3571.91,125.09) C17.2@3571.91,209 v1(3571.91,284.91) ; D12.2@3826,831.51 v1(3826,900)
  other v1: 3419,853 3419,894 3419,935 3103,1105 3103,1146
GND_OPT: J22.3 U12.3 | length 396.8
  Top Layer w20: J22.3@2588,149.5 2534,203.5 2534,378 2613.98,457.98 U12.3@2613.98,490.77
GND_PS: C1.2 C2.2 C3.2 C4.2 C5.2 C6.2 C7.1 C8.2 J4.2 J5.2 R2.1 R4.1 U1.3 U2.3 U3.2 | length 1554.1
  Top Layer w20: v1(398,1297) 399,1298 C3.2@460,1298 ; v1(398,1857) 399,1858 C5.2@460,1858 ; v1(460,1240) C3.2@460,1298 ; v1(460,1800) C5.2@460,1858 ; U1.3@558.87,1314.6 524.6,1314.6 508,1298 C3.2@460,1298 ; U2.3@558.87,1874.6 524.6,1874.6 508,1858 C5.2@460,1858 ; v1(890,1389.6) 890.09,1389.51 1055.91,1389.51 v1(1056,1389.6) ; v1(890,1950) 890.09,1949.91 C1.2@972,1949.91 1055.91,1949.91 v1(1056,1950) ; v1(1010,1229.6) 1010,1288.6 v1(1065,1288.6) ; v1(1010,1790) C4.2@1010,1849 v1(1065,1849) ; v1(1247,1622) 1248.11,1620.89 C7.1@1302.89,1620.89 v1(1302.89,1568.89) ; v1(1336.33,1424) C8.2@1390.33,1424 R4.1@1390.33,1517 ; v1(1336.33,1517) R4.1@1390.33,1517 ; U3.2@1433.89,1610.69 1433.89,1575.47 1390.33,1531.91 R4.1@1390.33,1517 ; v1(1487.89,1864.89) R2.1@1487.89,1801.89 1543.89,1801.89 v1(1545,1803)
  other v1: 398,1240 398,1800
GND_RS: C9.2 C10.1 C12.2 C13.2 C15.1 C16.2 J10.2 J14.2 R21.1 R24.1 U4.3 U6.3 | length 583.4
  Top Layer w20: C12.2@1266.89,527 v1(1266.89,583.11) ; C16.2@1267.49,1115.6 v1(1267.49,1171.71) ; R24.1@1410.24,1206.62 v1(1449.62,1206.62) ; R21.1@1410.62,619 v1(1450,619) ; v1(1467.98,122.81) C9.2@1467.98,204 ; v1(1467.98,710.81) C13.2@1467.98,792 ; v1(1544,412) v1(1659,412) ; v1(1598.89,1054.89) C15.1@1598.89,1000 v1(1659,1000)
GND_WDT: C11.2 C14.2 D11.2 J9.2 J11.3 R15.2 S1.1 TP11.1 U5.4 U5.9 | length 168.8
  Top Layer w20: S1.1@715.68,399 v1(715.68,466.32) ; v1(790,341) R15.2@790,399 ; v1(1028.51,923.49) D11.2@1028.51,967
  other v1: 359,503 398,503 359,547 398,547 626,681
  other v2: 622.43,557.11 661.8,557.11 622.43,596.48 661.8,596.48
I_TD_IN1: D2.2 D6.1 J18.1 U7.4 U7.5 U7.6 | length 98
  Top Layer w20: 3503.39,1644.47 U7.4@3503.39,1666.13 U7.6@3503.39,1717.31 3503.39,1742.51
I_TD_IN2: D3.2 D7.1 J18.2 U9.4 U9.5 U9.6 | length 12.7
  Top Layer w20: D7.1@3163.26,1531.74 D7.1@3176,1531.74
  other v1: 3278,1100 3319,1100 3278,1141 3319,1141 3156,1619 3197,1619 3156,1660 3197,1660
NetC1_1: C1.1 J1.1 | length 160.1
  Top Layer w25: J1.1@818,2049.4 832.69,2064.09 C1.1@972,2064.09
NetC2_1: C2.1 J3.1 | length 160.1
  Top Layer w25: J3.1@818,1489 832.69,1503.69 C2.1@972,1503.69
NetC4_1: C4.1 J1.3 | length 112.2
  Top Layer w20: J1.3@818,1849.4 818.4,1849 C4.1@930,1849
NetC6_1: C6.1 J3.3 | length 112.2
  Top Layer w20: J3.3@818,1289 818.4,1288.6 C6.1@930,1288.6
NetC7_2: C7.2 J6.2 U3.6 | length 228.7
  Top Layer w20: J6.2@1172.89,1702.89 1174.89,1700.89 C7.2@1302.89,1700.89 1313.09,1711.09 U3.6@1396.49,1711.09
NetC8_1: C8.1 R3.1 R4.2 U3.3
NetC9_1: C9.1 J8.1 | length 119.2
  Top Layer w20: J8.1@1241.49,220.6 1337.21,220.6 C9.1@1353.81,204
NetC12_1: C12.1 J8.3 | length 129.4
  Top Layer w20: C12.1@1186.89,527 1186.89,474 J8.3@1240.89,420
NetC13_1: C13.1 J12.1 | length 119.2
  Top Layer w20: J12.1@1241.49,808.6 1337.21,808.6 C13.1@1353.81,792
NetC14_1: C14.1 J13.1 | length 124.4
  Top Layer w20: J13.1@679,888 679,765 C14.1@680,764
NetC16_1: C16.1 J12.3 | length 129.4
  Top Layer w20: C16.1@1187.49,1115.6 1187.49,1062.6 J12.3@1241.49,1008.6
